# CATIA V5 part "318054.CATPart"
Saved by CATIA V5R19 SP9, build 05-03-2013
Part number: 318054
Source: Unknown
Bounding box of the stored display mesh (mm): x -107.69 to 242.5, y -243 to -193.848, z 495.8 to 596.5
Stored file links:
  D:\16-SIL\kale oto\R19_V1\318054.CATPart
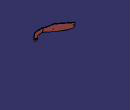
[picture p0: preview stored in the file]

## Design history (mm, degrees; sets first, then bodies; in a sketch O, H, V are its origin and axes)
Body1 "157\\124\\MANIFOLD_SOLID_BREP #74638" (main body)
  Solid1: solid without history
